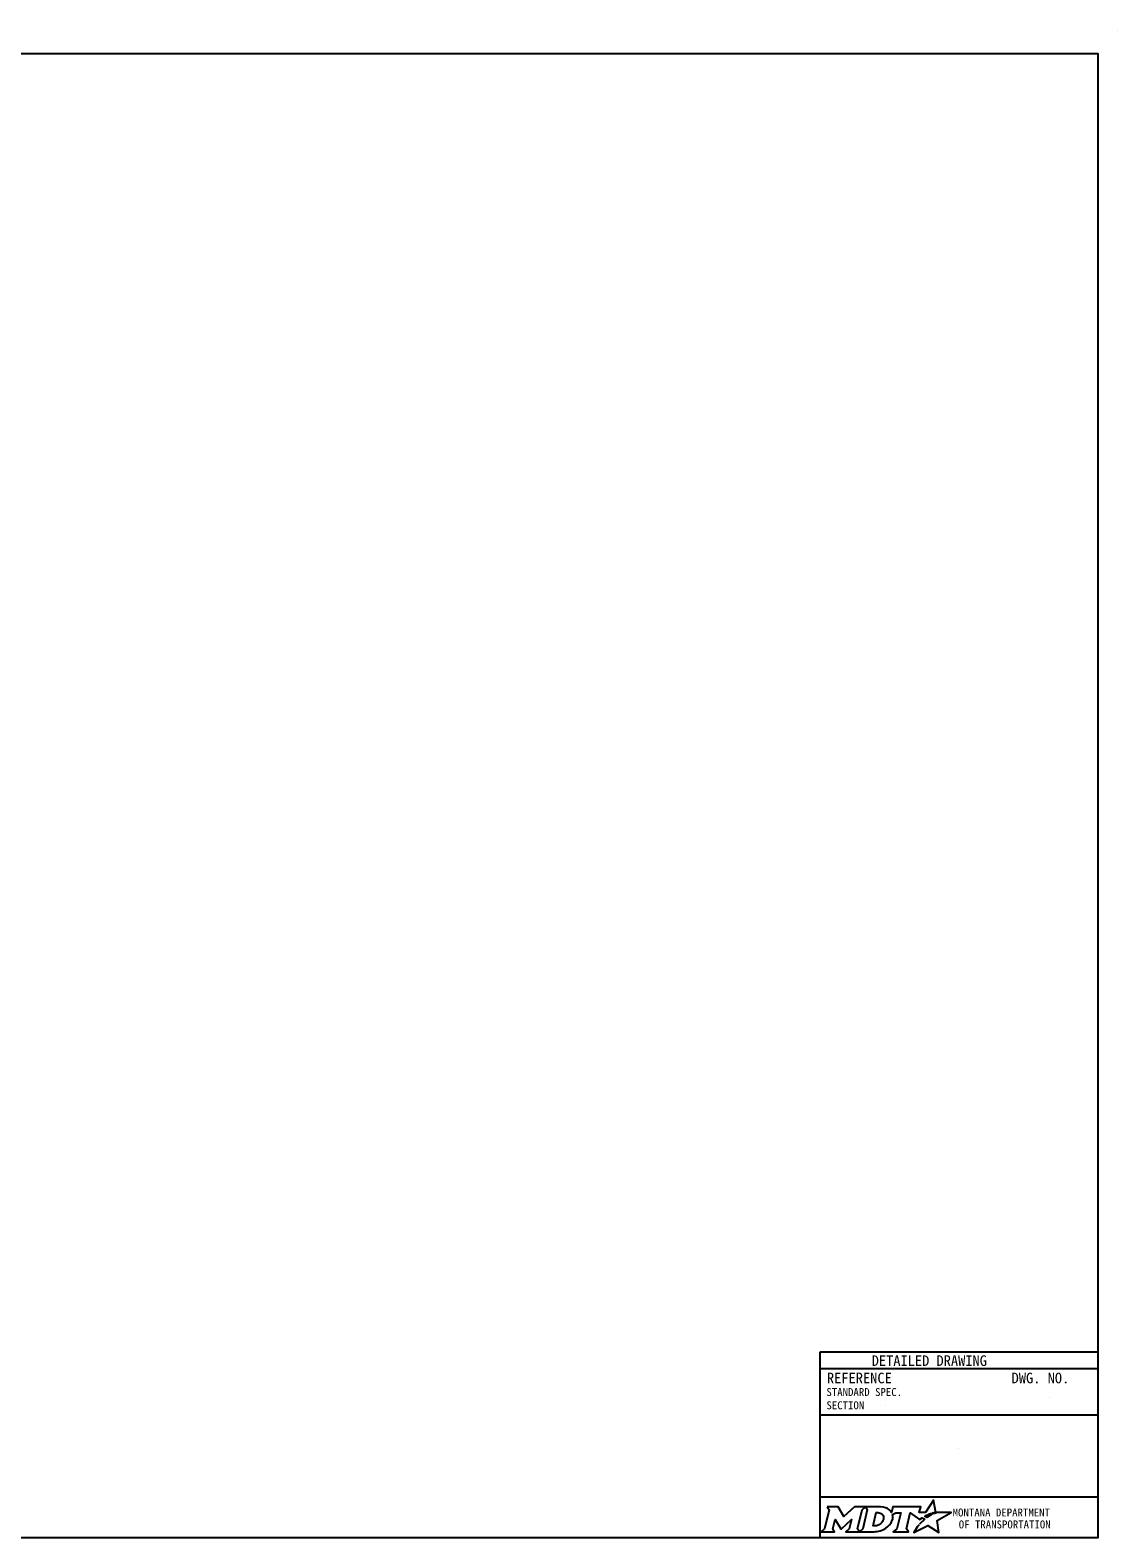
# Model space of a CAD drawing. Extents: x 49991.4 to 50021, y 49987.6 to 50011.4.
# Drawn here: x 50008.69 to 50016.9, y 49987.8 to 49999.18 of the extents above; entities that cross this region are included whole.
import ezdxf

# ---------------------------------------------------------------- set-up
doc = ezdxf.new("R2010")
doc.units = 0
for name, color, linetype in [('Default', 7, 'Continuous'), ('Level 1', 7, 'Continuous'), ('Level 5', 7, 'Continuous')]:
    doc.layers.add(name, color=color, linetype=linetype)

msp = doc.modelspace()

# ---------------------------------------------------------------- linework, layer by layer
at = {"layer": 'Default'}
for points in [[(50015.513, 49987.981), (50015.502, 49987.987), (50015.514, 49987.99), (50015.526, 49987.991), (50015.508, 49988.082), (50015.449, 49987.99), (50015.401, 49987.99), (50015.412, 49988.034), (50015.202, 49988.034), (50015.192, 49987.991), (50015.186, 49988)], [(50014.706, 49988.034), (50014.72, 49988.01), (50014.686, 49987.867), (50014.66, 49987.845), (50014.762, 49987.845), (50014.749, 49987.867), (50014.765, 49987.937), (50014.809, 49987.868), (50014.814, 49987.868), (50014.889, 49987.938), (50014.872, 49987.867), (50014.848, 49987.845), (50014.949, 49987.845), (50014.936, 49987.868), (50014.969, 49988.011)], [(50014.969, 49988.011), (50014.994, 49988.034), (50014.912, 49988.034), (50014.832, 49987.961), (50014.788, 49988.034), (50014.706, 49988.034)], [(50015.108, 49988.034), (50014.994, 49988.034), (50015.009, 49988.011), (50014.975, 49987.867), (50014.949, 49987.845), (50015.06, 49987.845)], [(50015.132, 49987.947), (50015.13, 49987.939), (50015.127, 49987.93), (50015.123, 49987.922), (50015.118, 49987.914), (50015.111, 49987.907), (50015.103, 49987.901), (50015.095, 49987.896), (50015.086, 49987.892), (50015.077, 49987.89), (50015.067, 49987.889), (50015.052, 49987.889), (50015.075, 49987.989), (50015.091, 49987.989), (50015.099, 49987.988), (50015.106, 49987.986), (50015.113, 49987.983), (50015.119, 49987.979), (50015.124, 49987.974), (50015.128, 49987.968), (50015.13, 49987.962), (50015.132, 49987.955), (50015.132, 49987.952), (50015.132, 49987.947)], [(50015.199, 49987.975), (50015.224, 49987.988), (50015.261, 49987.988), (50015.232, 49987.867), (50015.205, 49987.845), (50015.321, 49987.845), (50015.304, 49987.867), (50015.332, 49987.988), (50015.403, 49987.936), (50015.424, 49987.951), (50015.444, 49987.94)], [(50015.388, 49987.884), (50015.373, 49987.86), (50015.368, 49987.852), (50015.362, 49987.844), (50015.36, 49987.839), (50015.465, 49987.893), (50015.549, 49987.838), (50015.536, 49987.93), (50015.643, 49987.989), (50015.594, 49987.989), (50015.564, 49987.99), (50015.543, 49987.99), (50015.536, 49987.989), (50015.531, 49987.987), (50015.523, 49987.985), (50015.513, 49987.981)], [(50015.462, 49987.954), (50015.46, 49987.952), (50015.442, 49987.961), (50015.452, 49987.967), (50015.456, 49987.969), (50015.465, 49987.973), (50015.47, 49987.976), (50015.478, 49987.979), (50015.485, 49987.982), (50015.497, 49987.974), (50015.493, 49987.972), (50015.489, 49987.97), (50015.484, 49987.967), (50015.479, 49987.965), (50015.478, 49987.963), (50015.475, 49987.962), (50015.472, 49987.96), (50015.47, 49987.959), (50015.467, 49987.957), (50015.465, 49987.955), (50015.462, 49987.954)], [(50015.106, 49987.852), (50015.114, 49987.855), (50015.127, 49987.86), (50015.148, 49987.871)], [(50015.402, 49987.9), (50015.402, 49987.9)]]:
    msp.add_lwpolyline(points, dxfattribs=at)
for centre, radius, start, end in [((50015.087, 49987.973), 0.118, 300.9103, 339.1383), ((50015.131, 49987.955), 0.0709, 339.5329, 15.8582)]:
    msp.add_arc(centre, radius, start, end, dxfattribs=at)
for centre, major_axis, ratio, start_param, end_param in [((50015.106, 49987.986), (0.0834, -0.0037), 0.568097, 0.61298, 1.570796), ((50015.161, 49987.994), (0.0361, -0.0295), 0.469099, 1.225588, 1.570796), ((50015.433, 49987.93), (-0.0112, -0.0097), 0.021651, 3.157348, 6.283185), ((50015.06, 49987.993), (0, 0.148), 0.987302, 3.139398, 3.456847), ((50015.395, 49987.892), (-0.00694, -0.00806), 0.008222, 0, 3.137361), ((50015.412, 49987.911), (-0.0098, -0.0102), 0.016458, 3.141593, 6.279097)]:
    msp.add_ellipse(centre, major_axis=major_axis, ratio=ratio, start_param=start_param, end_param=end_param, dxfattribs=at)
at = {"layer": 'Level 1'}
msp.add_line((50016.9, 49999.176), (50016.9, 49999.176), dxfattribs=at)
msp.add_lwpolyline([(49999.384, 49998.999), (50016.75, 49998.999), (50016.75, 49987.799), (49999.384, 49987.799)], close=True, dxfattribs=at)
at = {"layer": 'Level 5'}
for p, q in [((50016.75, 49989.199), (50014.65, 49989.199)), ((50014.65, 49989.199), (50014.65, 49987.799)), ((50016.75, 49989.074), (50014.65, 49989.074)), ((50016.386, 49988.859), (50016.386, 49988.859)), ((50016.75, 49988.724), (50014.65, 49988.724)), ((50015.144, 49988.799), (50015.144, 49988.799)), ((50015.7, 49988.475), (50015.7, 49988.475)), ((50016.75, 49988.106), (50014.65, 49988.106))]:
    msp.add_line(p, q, dxfattribs=at)

# ---------------------------------------------------------------- texts
at = {"layer": 'Default'}
for s, p in [('MONTANA DEPARTMENT', (50015.653, 49987.96)), ('OF TRANSPORTATION', (50015.699, 49987.87))]:
    msp.add_text(s, height=0.06, rotation=360, dxfattribs=at).set_placement(p)
at = {"layer": 'Level 5'}
for s, height, p in [('DETAILED DRAWING', 0.0799, (50015.042, 49989.096)), ('REFERENCE', 0.08, (50014.704, 49988.965)), ('DWG. NO.', 0.08, (50016.098, 49988.965)), ('STANDARD SPEC.', 0.06, (50014.7, 49988.869)), ('SECTION', 0.06, (50014.7, 49988.769))]:
    msp.add_text(s, height=height, dxfattribs=at).set_placement(p)

doc.saveas('drawing.dxf')
